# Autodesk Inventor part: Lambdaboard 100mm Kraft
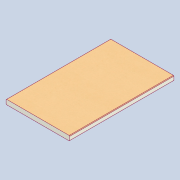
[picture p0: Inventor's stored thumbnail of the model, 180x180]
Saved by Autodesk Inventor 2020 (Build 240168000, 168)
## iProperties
Created: 2020-11
Part Number: Lambdaboard 100mm Kraft
Material: Polyisocyanurate
Document SubType Name: Modeling
Designer: Yolande
Density: 0.032 g/cm^3
Appearance: Pink
Author: Yolande
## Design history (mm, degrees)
sketch "Sketch1"
  geometry: L1 (10, 0)-(1210, 0); L2 (1220, 10)-(1220, 80); L3 (1210, 90)-(10, 90); L4 (0, 80)-(0, 10); A1 r 10 centre (10, 80) between (10, 90) and (0, 80); A2 r 10 centre (10, 10) between (0, 10) and (10, 0); A3 r 10 centre (1210, 80) between (1220, 80) and (1210, 90); A4 r 10 centre (1210, 10) between (1210, 0) and (1220, 10); 3 further points
  constraints: 8 end point, 8 point on circle, 8 tangent, 6 point on line, 4 centre point, 3 equal radius, 3 perpendicular, 1 horizontal
  dimensions: "d0" = 1220 distance of point (0, 0) point (1220, 0); "d1" = 90 distance of point (1220, 0) point (1220, 90); "d2" = 10 radius of A1
extrude "Extrusion1" new body sketch "Sketch1" distance "d3" = 2000; taper "d4" = 0 deg
body "Solid1"
